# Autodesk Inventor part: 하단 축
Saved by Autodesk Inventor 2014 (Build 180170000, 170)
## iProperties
Created: 2024-05
Part Number: 하단 축
Material: 일반
Document SubType Name: Modeling
Designer: dg
Density: 1 g/cm^3
Appearance: 기본값
Author: dg
Author: jhkim
Creation Date: 2024-05-07
Sending System: Autodesk Inventor 2025
Preprocessor: ST-DEVELOPER v20
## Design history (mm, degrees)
node "하단 축1"
node "솔리드1"
node "기준1"
